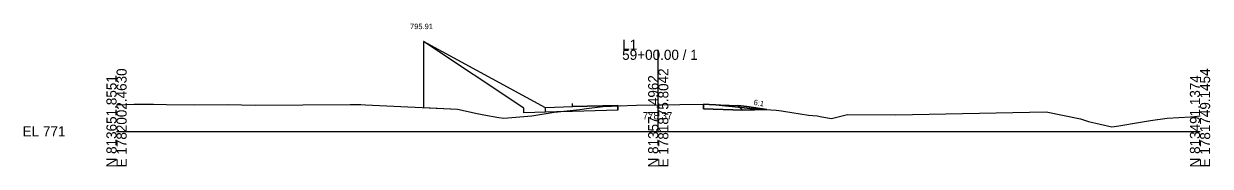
# Model space of a CAD drawing. Extents: x 5574 to 10203, y -10 to 9546.
# Drawn here: x 6574.3 to 6902.8, y 5990.3 to 6029.9 of the extents above; entities that cross this region are included whole.
import ezdxf

# ---------------------------------------------------------------- set-up
doc = ezdxf.new("R2010")
doc.units = 0
for name, color, linetype in [('Exist Cross Section Cell', 7, 'Continuous'), ('Exist XS Center Line Elevation Label', 7, 'Continuous'), ('Exist XS Ground Line', 7, 'Continuous'), ('Prop XS Ditch Slope Text', 7, 'Continuous'), ('Prop XS Ditch Standard Text', 7, 'Continuous'), ('Prop XS Dump Level', 7, 'Continuous'), ('Prop XS Earthwork Shape', 7, 'Continuous'), ('Prop XS EOT Tick Mark', 7, 'Continuous'), ('Prop XS Finish Grade', 7, 'Continuous'), ('Prop XS Finish Grade Earthwork', 7, 'Continuous'), ('Prop XS Finish Grade Paved Shoulder', 7, 'Continuous'), ('Prop XS Finish Grade Pavement', 7, 'Continuous'), ('Prop XS Pvmt Edge Slope', 7, 'Continuous'), ('Prop XS Subgrade Earthwork', 7, 'Continuous'), ('Scratch_Level_3', 7, 'Continuous'), ('Scratch_Level_6', 7, 'Continuous')]:
    doc.layers.add(name, color=color, linetype=linetype)

msp = doc.modelspace()

# ---------------------------------------------------------------- linework, layer by layer
at = {"layer": 'Exist Cross Section Cell'}
for p, q in [((6750, 6000), (6750, 6022.66)), ((6600, 6000), (6750, 6000)), ((6750, 6000), (6900, 6000))]:
    msp.add_line(p, q, dxfattribs=at)
at = {"layer": 'Exist XS Ground Line'}
for p, q in [((6600, 6007.4), (6604.92, 6007.53)), ((6604.92, 6007.53), (6610.21, 6007.55)), ((6610.21, 6007.55), (6613.8, 6007.47)), ((6613.8, 6007.47), (6621.65, 6007.39)), ((6621.65, 6007.39), (6630.73, 6007.44)), ((6630.73, 6007.44), (6638.44, 6007.27)), ((6638.44, 6007.27), (6664.72, 6007.48)), ((6664.72, 6007.48), (6667.68, 6007.45)), ((6667.68, 6007.45), (6668.94, 6007.41)), ((6668.94, 6007.41), (6694.38, 6006.18)), ((6694.38, 6006.18), (6699.83, 6004.95)), ((6722.18, 6005.46), (6723.87, 6005.65)), ((6723.87, 6005.65), (6728.32, 6006.09)), ((6728.32, 6006.09), (6730.17, 6006.36)), ((6730.17, 6006.36), (6734.64, 6006.9)), ((6734.64, 6006.9), (6737.07, 6007.02)), ((6737.07, 6007.02), (6738.87, 6007.12)), ((6738.87, 6007.12), (6743.94, 6007.24)), ((6743.94, 6007.24), (6750, 6007.37)), ((6750, 6007.37), (6750.93, 6007.39)), ((6750.93, 6007.39), (6755.93, 6007.46)), ((6755.93, 6007.46), (6762.51, 6007.53)), ((6762.51, 6007.53), (6764.08, 6007.46)), ((6764.08, 6007.46), (6765.92, 6007.36)), ((6765.92, 6007.36), (6772.19, 6006.71)), ((6772.19, 6006.71), (6775.31, 6006.36)), ((6775.31, 6006.36), (6782.69, 6005.86)), ((6782.69, 6005.86), (6783.37, 6005.82)), ((6783.37, 6005.82), (6784.11, 6005.72)), ((6784.11, 6005.72), (6784.64, 6005.62)), ((6784.64, 6005.62), (6791.57, 6004.54)), ((6699.83, 6004.95), (6700.34, 6004.83)), ((6700.34, 6004.83), (6701.74, 6004.58)), ((6701.74, 6004.58), (6705.86, 6003.85)), ((6705.86, 6003.85), (6707.28, 6003.63)), ((6707.28, 6003.63), (6709.47, 6003.84)), ((6709.47, 6003.84), (6715, 6004.34)), ((6715, 6004.34), (6721.18, 6005.31)), ((6721.18, 6005.31), (6722.18, 6005.46)), ((6791.57, 6004.54), (6793.96, 6004.28)), ((6793.96, 6004.28), (6795.32, 6004.02)), ((6795.32, 6004.02), (6797.98, 6003.57)), ((6797.98, 6003.57), (6802.44, 6004.69)), ((6802.44, 6004.69), (6815.77, 6004.61)), ((6815.77, 6004.61), (6857.37, 6005.46)), ((6857.37, 6005.46), (6866.91, 6003.49)), ((6866.91, 6003.49), (6869.16, 6002.75)), ((6869.16, 6002.75), (6872.33, 6001.97)), ((6877.48, 6001.57), (6882.98, 6002.44)), ((6882.98, 6002.44), (6886.32, 6003.01)), ((6886.32, 6003.01), (6890.86, 6003.66)), ((6890.86, 6003.66), (6897.35, 6004.05)), ((6897.35, 6004.05), (6898.5, 6004.14)), ((6898.5, 6004.14), (6900, 6004.3)), ((6872.33, 6001.97), (6875.63, 6001.28)), ((6875.63, 6001.28), (6877.48, 6001.57))]:
    msp.add_line(p, q, dxfattribs=at)
at = {"layer": 'Prop XS Dump Level'}
msp.add_line((6738.85, 6007.15), (6726.26, 6006.9), dxfattribs=at)
msp.add_line((6738.85, 6007.15), (6726.26, 6006.9), dxfattribs=at)
at = {"layer": 'Prop XS Earthwork Shape'}
for points in [[(6700.34, 6004.83), (6701.74, 6004.58), (6705.86, 6003.85), (6707.28, 6003.63), (6709.47, 6003.84), (6715, 6004.34), (6721.18, 6005.31), (6721.83, 6005.41), (6712.76, 6005.17), (6712.76, 6006.42), (6685.02, 6024.91), (6685.02, 6006.63), (6694.38, 6006.18), (6699.83, 6004.95)], [(6726.26, 6005.53), (6721.83, 6005.41), (6722.18, 6005.46), (6723.87, 6005.65), (6728.32, 6006.09), (6730.17, 6006.36), (6734.64, 6006.9), (6737.07, 6007.02), (6738.85, 6007.12), (6738.85, 6005.87)], [(6762.53, 6006.28), (6762.53, 6007.53), (6764.08, 6007.46), (6765.92, 6007.36), (6772.19, 6006.71), (6775.31, 6006.36), (6780.03, 6006.04), (6773.34, 6005.85)]]:
    msp.add_lwpolyline(points, close=True, dxfattribs=at)
at = {"layer": 'Prop XS EOT Tick Mark'}
msp.add_line((6726.26, 6006.78), (6726.26, 6007.78), dxfattribs=at)
at = {"layer": 'Prop XS Finish Grade'}
for p, q in [((6772.04, 6007.15), (6774.53, 6006.95)), ((6774.53, 6006.95), (6780.03, 6006.04))]:
    msp.add_line(p, q, dxfattribs=at)
at = {"layer": 'Prop XS Finish Grade Earthwork'}
for p, q in [((6718.76, 6006.58), (6685.02, 6024.91)), ((6685.02, 6024.91), (6685.02, 6006.63))]:
    msp.add_line(p, q, dxfattribs=at)
at = {"layer": 'Prop XS Finish Grade Paved Shoulder'}
msp.add_line((6726.26, 6006.78), (6718.76, 6006.58), dxfattribs=at)
at = {"layer": 'Prop XS Finish Grade Pavement'}
for p, q in [((6738.85, 6007.12), (6726.26, 6006.78)), ((6762.53, 6007.53), (6772.04, 6007.15))]:
    msp.add_line(p, q, dxfattribs=at)
at = {"layer": 'Prop XS Pvmt Edge Slope'}
msp.add_line((6772.04, 6007.15), (6773.34, 6005.85), dxfattribs=at)
at = {"layer": 'Prop XS Subgrade Earthwork'}
for p, q in [((6718.76, 6005.33), (6718.76, 6006.58)), ((6738.85, 6005.87), (6726.26, 6005.53)), ((6738.85, 6005.87), (6738.85, 6007.12)), ((6762.53, 6006.28), (6762.53, 6007.53)), ((6762.53, 6006.28), (6773.34, 6005.85)), ((6773.34, 6005.85), (6780.03, 6006.04)), ((6726.26, 6005.53), (6718.76, 6005.33))]:
    msp.add_line(p, q, dxfattribs=at)
at = {"layer": 'Scratch_Level_3'}
for p, q in [((6774.53, 6006.95), (6772.04, 6007.15)), ((6772.04, 6007.15), (6773.34, 6005.85)), ((6773.34, 6005.85), (6780.03, 6006.04)), ((6780.03, 6006.04), (6774.53, 6006.95))]:
    msp.add_line(p, q, dxfattribs=at)
at = {"layer": 'Scratch_Level_6'}
for points in [[(6723.87, 6005.65), (6728.32, 6006.09), (6730.17, 6006.36), (6734.64, 6006.9), (6737.07, 6007.02), (6738.85, 6007.12), (6738.85, 6005.87), (6726.26, 6005.53), (6721.83, 6005.41), (6722.18, 6005.46)], [(6762.53, 6006.28), (6773.34, 6005.85), (6780.03, 6006.04), (6775.31, 6006.36), (6772.19, 6006.71), (6765.92, 6007.36), (6764.08, 6007.46), (6762.53, 6007.53)]]:
    msp.add_lwpolyline(points, close=True, dxfattribs=at)

# ---------------------------------------------------------------- texts
at = {"layer": 'Exist Cross Section Cell'}
for s, p in [('L1', (6740, 6022.66)), ('59+00.00 / 1', (6740, 6019.86)), ('EL 771', (6574, 5998.6))]:
    msp.add_text(s, height=2.8, dxfattribs=at).set_placement(p)
for s, p in [('E 1782002.4630', (6602.8, 5990)), ('E 1781875.8042', (6752.8, 5990)), ('N 813491.1374', (6900, 5990)), ('E 1781749.1454', (6902.8, 5990)), ('N 813651.8551', (6600, 5990)), ('N 813571.4962', (6750, 5990))]:
    msp.add_text(s, height=2.8, rotation=90, dxfattribs=at).set_placement(p)
at = {"layer": 'Exist XS Center Line Elevation Label'}
msp.add_text('778.37', height=2, dxfattribs=at).set_placement((6745.7, 6003.37))
at = {"layer": 'Prop XS Ditch Slope Text'}
msp.add_text('6:1', height=1.5, rotation=350.5377, dxfattribs=at).set_placement((6776.32, 6007.38))
at = {"layer": 'Prop XS Ditch Standard Text'}
msp.add_text('795.91', height=1.5, dxfattribs=at).set_placement((6681.27, 6028.38))
at = {"layer": 'Prop XS Dump Level'}
msp.add_text('Eop', height=0.3, dxfattribs=at).set_placement((6738.85, 6006.82))

doc.saveas('drawing.dxf')
